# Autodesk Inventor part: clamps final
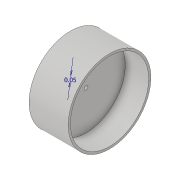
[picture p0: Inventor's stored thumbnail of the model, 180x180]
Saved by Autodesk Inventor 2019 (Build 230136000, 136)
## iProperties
Created: 2020-02
Part Number: clamps final
Material: Generic
Document SubType Name: Modeling
Designer: Krupashree
Density: 1 g/cm^3
Appearance: Default
Author: Krupashree
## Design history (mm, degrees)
sketch "Sketch1"
  geometry: C1 r 5.281 at (0, 0); 1 further point
  constraints: 1 centre point
extrude "Extrusion1" new body sketch "Sketch1" distance "d1" = 5; taper "d2" = 0 deg
sketch "Sketch2"
  geometry: C1 r 5.005 at (0, 0); 1 further point
  constraints: 1 centre point, 1 coincident
extrude "Extrusion2" cut sketch "Sketch2" distance "d3" = 3; taper "d4" = 0 deg
sketch "Sketch3"
  geometry: C1 r 0.25 at (0, 0); 1 further point
  constraints: 1 centre point, 1 coincident
  dimensions: "d5" = 0.5 diameter of C1
extrude "Extrusion3" cut sketch "Sketch3" distance "d6" = 3; taper "d7" = 0 deg
sketch "Sketch4"
  geometry: C1 r 0.25 at (0, 0); 1 further point
  constraints: 1 centre point, 1 coincident
  dimensions: "d8" = 0.5 diameter of C1
body "Solid1"
